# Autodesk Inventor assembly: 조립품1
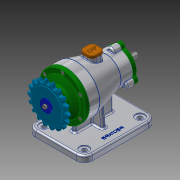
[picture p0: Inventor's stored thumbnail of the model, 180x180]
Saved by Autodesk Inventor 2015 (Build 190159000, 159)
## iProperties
Created: 2021-10
Part Number: 조립품1
Document SubType Name: Assembly
Designer: 1019876
Author: 1019876
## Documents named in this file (16)
- C:\Users\1019876\Desktop\711006V1019\조립품1.iam
- C:\Users\1019876\Desktop\711006V1019\본체.ipt
- C:\Users\1019876\Desktop\711006V1019\축.ipt
- C:\Users\1019876\Desktop\711006V1019\베어링 6203.ipt
- C:\Users\1019876\Desktop\711006V1019\앞커버.ipt
- C:\Users\1019876\Desktop\711006V1019\오일 실 17x30x8.ipt
- C:\Users\1019876\Desktop\711006V1019\키 5x5.ipt
- 키 5 x 5.ipt
- C:\Users\1019876\Desktop\711006V1019\스프로킷.ipt
- C:\Users\1019876\Desktop\711006V1019\와셔.ipt
- C:\Users\1019876\Desktop\711006V1019\볼트 M4.ipt
- 볼트 M4 x 12.ipt
- C:\Users\1019876\Desktop\711006V1019\베어링 6200.ipt
- C:\Users\1019876\Desktop\711006V1019\뒤커버.ipt
- C:\Users\1019876\Desktop\711006V1019\오일 실 10x20x7.ipt
- C:\Users\1019876\Desktop\711006V1019\마개.ipt
